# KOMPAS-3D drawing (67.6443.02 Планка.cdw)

Referenced files: Планка2.cdw
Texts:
  Планка
  *Размер для справок.
  Кромки А и Б заострить.
  Неуказанные радиусы закругления 10 мм.
  Нач. КО
Dimensions and other numbers on the sheet: 84; 8; 19; 125; 38; 10; 20; 15; 2 отв.; 4; 85; 6,3; 1:1; 0,125; 1; 0; 2; 3; 5; 6; 7; 9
